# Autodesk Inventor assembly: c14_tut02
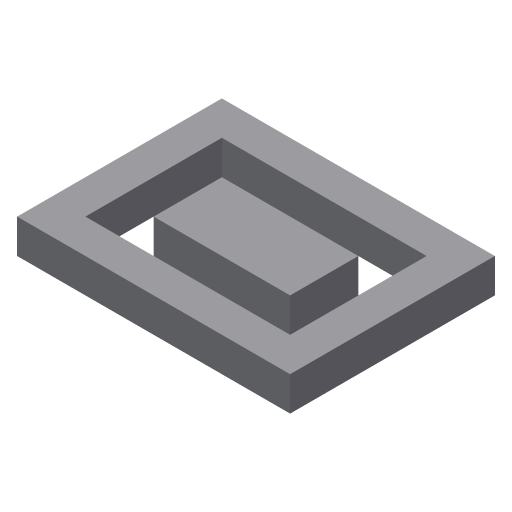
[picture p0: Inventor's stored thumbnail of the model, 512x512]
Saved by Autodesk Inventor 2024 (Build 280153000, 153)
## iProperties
Created: 2010-04
Part Number: c14_tut02
Document SubType Name: Assembly
Designer: CADSoft
Author: CADSoft
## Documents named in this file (3)
- D:\PROJECTS\Project 2023\RESOURCES INVENTOR 2024\RESOURCES INVENTOR 2024\Inventor_2024_tut\Inventor_2024_tut\c18_Inv_2024_tut\c18_Inv_tut_2024\c18_tut02_inv\c18_tut02_inv.iam
- D:\PROJECTS\Project 2023\RESOURCES INVENTOR 2024\RESOURCES INVENTOR 2024\Inventor_2024_tut\Inventor_2024_tut\c18_Inv_2024_tut\c18_Inv_tut_2024\c18_tut02_inv\Outer Plate.ipt
- D:\PROJECTS\Project 2023\RESOURCES INVENTOR 2024\RESOURCES INVENTOR 2024\Inventor_2024_tut\Inventor_2024_tut\c18_Inv_2024_tut\c18_Inv_tut_2024\c18_tut02_inv\Inner Plate.ipt
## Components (2 placed, 2 different names)
1. Outer Plate:1 — Flush:1, Flush:2, Mate:1, Mate:2, Mate:3, Mate:4
2. Inner Plate:1 — Flush:1, Flush:2, Mate:1, Mate:2, Mate:3, Mate:4
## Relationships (6: Mate 4, Flush 2)
- Flush:1: Outer Plate:1 ↔ Inner Plate:1
- Flush:2: Outer Plate:1 ↔ Inner Plate:1
- Mate:1: Outer Plate:1 ↔ Inner Plate:1
- Mate:2: Outer Plate:1 ↔ Inner Plate:1
- Mate:3: Outer Plate:1 ↔ Inner Plate:1
- Mate:4: Outer Plate:1 ↔ Inner Plate:1
